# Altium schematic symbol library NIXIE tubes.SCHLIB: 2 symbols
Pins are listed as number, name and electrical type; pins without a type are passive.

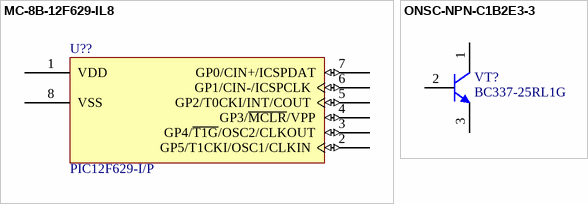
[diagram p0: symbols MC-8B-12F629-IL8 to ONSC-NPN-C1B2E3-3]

## MC-8B-12F629-IL8
designator U??, comment PIC12F629-I/P
FLASH-Based 8-Bit CMOS Microcontroller, 8-Pin PDIP, Industrial Temperature; Note1: Refer to data sheet (DS41190F) for details of supply voltage range under different conditions.
footprint PDIP300-P8 (DIP, 8-Leads, Row Spacing 7.62mm, Pitch 2.54mm, Body 9.5x6.6mm)
pins: 1 VDD (power), 2 GP5/T1CKI/OSC1/CLKIN (io), 3 GP4/~{T1G}/OSC2/CLKOUT (io), 4 GP3/~{MCLR}/VPP (io), 5 GP2/T0CKI/INT/COUT (io), 6 GP1/CIN-/ICSPCLK (io), 7 GP0/CIN+/ICSPDAT (io), 8 VSS (power)

## ONSC-NPN-C1B2E3-3
designator VT?, comment BC337-25RL1G
Amplifier Transistor, NPN Silicon, 3-Pin TO-92, Pb-Free, Tape and Reel; Manufacturer: On Semiconductor; IC Continuous (A): 0.8
footprint ONSC-TO-92-3-29-11_AM_BL (TO, 3-Leads, Body Dia 4.7mm, Pitch 2.6mm)
pins: 1 C, 2 B, 3 E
